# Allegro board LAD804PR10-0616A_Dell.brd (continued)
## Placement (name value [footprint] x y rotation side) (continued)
H7  HOLEA  [H_3P0N]  3 122.3 0 top
H8  HOLEA  [H_3P5-G]  86.9 111.6 0 top
H9  HOLEA  [H_3P5-G]  113.5 134.5 0 top
H10  HOLEA  [H_3P5-G]  136.5 90.5 0 top
H11  HOLEA  [H_3P2]  52.3 133.7 0 top
H12  HOLEA  [H_3P2X2P6]  5 3.6 90 top
H13  HOLEA  [H_6P0]  121.2 136 0 top
HCPU1  HOLEA  [H_3P7X4P3]  101.96 76.01 0 top
HCPU2  HOLEA  [H_3P7]  101.96 31.01 0 top
HCPU3  HOLEA  [H_3P9]  127.36 76.01 0 top
HCPU4  HOLEA  [H_3P7X4P3]  127.36 31.01 90 top
J10  -  [JUMP_43X79]  155.72 18.86 270 bottom
J11  -  [JUMP_43X118]  97.98 98.7 180 bottom
J509  -  [JUMP_43X118]  164.36 5.31 90 bottom
J510  -  [JUMP_43X79]  159.53 5.31 90 bottom
J511  -  [JUMP_43X118]  152.38 25.42 0 bottom
JDIMM1  DEREN_40-42271-26001RHF  [DEREN_40-42271-26001RHF_260P-T]  70.12 87.13 270 bottom
JDIMM2  DEREN_40-42261-26001RHF  [DEREN_40-42261-26001RHF_260P-T]  53.05 87.62 90 bottom
JEDP1  ACES_51540-04001-P01  [ACES_51540-04001-P01_40P]  224.08 50.05 270 bottom
JFAN1  JXT_WB247H-004S10M  [JXT_WB247H-004S10M_4P]  182.74 52.09 47.5 bottom
JH1  ACES_91960-0084N_MX25L3206EM2I  [ACES_91960-0084L_8P-T]  112.17 17.67 270 bottom
JHDD1  ACES_51625-01201-001  [ACES_51625-01201-001_12P]  199.15 17.15 180 bottom
JHDMI1  CONCR_099AKAC19NBLCNF  [CONCR_099AKAC19NBLCNF_19P]  10.45 82.5 90 bottom
JHDT1  SAMTE_ASP-136446-07-B  [SAMTE_ASP-136446-07-B_20P-T]  91.53 70.76 90 top
JHP1  YUQIU_PJ753-F07J1BE-B  [YUQIU_PJ753-F07J1BE-B_7P-T]  11.55 13.52 90 bottom
JIOB1  ACES_51524-0160N-001  [ACES_51524-0160N-001_16P]  185.6 17.6 180 bottom
JKB1  STARC_132C30-100020-A2-R  [STARC_132C30-100020-A2-R_30P]  87.8 9.25 180 bottom
JKBBL1  ACES_51575-00401-001  [ACES_51575-00401-001_4P-T]  116.1 8.72 180 bottom
JLAN1  SANTA_130460-N  [SANTA_130460-N_8P-T]  12.85 113.27 90 bottom
JLED1  ACES_51524-0040N-001  [ACES_51524-0040N-001_4P]  153.7 12.28 180 bottom
JODD1  ACES_50673-0120N-001  [ACES_50673-0120N-001_12P-T]  187.5 47.7 180 bottom
JP2  -  [JUMP_43X39]  114.07 92.78 90 bottom
JP3  2MM  [JUMP_43X39]  28.47 120.72 90 bottom
JP7  -  [JUMP_43X79]  200.47 48.79 180 top
JP12  -  [JUMP_43X39]  36.04 3.32 180 bottom
JP13  -  [JUMP_43X79]  194.84 11.91 90 top
JP14  -  [JUMP_43X39]  37.66 3.32 0 bottom
JPWR1  JXT_FP226H-006S1BM  [JXT_FP226H-006S1BM_6P]  159.15 107.31 90 top
JRTC1  ACES_50271-0020N-001  [ACES_50271-0020N-001_2P]  29.83 5.9 180 bottom
JSPK1  JXT_WB247H-004S10M  [JXT_WB247H-004S10M_4P]  11.8 5.67 180 bottom
JTP1  JXT_FP202DH-008M10M  [JXT_FP202DH-008M10M_8P]  104.9 9.65 180 bottom
JUSB1  ACON_TARA4-9K1311  [ACON_TARA4-9K1311_9P]  14.68 63.2 90 bottom
JUSB2  ACON_TARA4-9K1311  [ACON_TARA4-9K1311_9P]  14.68 41.5 90 bottom
JWLAN1  LCN_DAN05-67406-0100  [LCN_DAN05-67406-0100_67P]  43.05 100.18 0 bottom
L3  MCM1012B900F06BP_4P  [INPAQ_MCM1012B900F06BP_4P]  220.63 34.06 0 bottom
LA1  BLM15BB221SN1D_2P  [MURAT_BLM15BB221SN1D_2P]  29.91 35.07 180 top
LA3  TAI-TECH HCB1005KF-800T20 0402  [R_0402]  35.64 31.26 0 top
LA4  TAI-TECH HCB1005KF-800T20 0402  [R_0402]  35.64 29.99 0 top
LA5  TAI-TECH HCB1005KF-800T20 0402  [R_0402]  35.64 27.45 0 top
LA6  TAI-TECH HCB1005KF-800T20 0402  [R_0402]  35.64 28.72 0 top
LA7  BLM15PX330SN1D_2P  [MURAT_BLM15PX330SN1D_2P]  21.61 14.93 270 bottom
LA8  0_0402_5%  [R_0402]  22.63 13.36 90 top
LA9  0_0402_5%  [R_0402]  22.63 17.66 270 top
LA10  BLM15PX330SN1D_2P  [MURAT_BLM15PX330SN1D_2P]  21.61 17.66 270 bottom
LC22  FBMA-L11-201209-121LMA50T_0805  [KC_FBMA-L11-201209-121LMA50_2P]  86.63 37.09 270 top
LE3  FBMA-L11-160808-800LMT_0603  [KC_FBMA-L11-160808-800LMT_2P]  166.28 35.59 180 top
LE4  FBMA-L11-160808-800LMT_0603  [KC_FBMA-L11-160808-800LMT_2P]  168.54 26.05 180 top
LI1  HCM1012GH900BP_4P  [INPAQ_HCM1012GH900BP_4P]  18.95 85.46 0 top
LI2  HCM1012GH900BP_4P  [INPAQ_HCM1012GH900BP_4P]  17.81 88.09 0 top
LI3  HCM1012GH900BP_4P  [INPAQ_HCM1012GH900BP_4P]  17.87 82.46 0 top
LI4  HCM1012GH900BP_4P  [INPAQ_HCM1012GH900BP_4P]  18.83 79.77 0 top
LU1  HCM1012GD670A05P_4P  [INPAQ_HCM1012GD670A05P_4P]  22.25 58.43 0 top
LU2  HCM1012GD670A05P_4P  [INPAQ_HCM1012GD670A05P_4P]  22.25 60.47 0 top
LU3  MCM1012B900F06BP_4P  [INPAQ_MCM1012B900F06BP_4P]  24.24 55.39 0 top
LU4  HCM1012GD670A05P_4P  [INPAQ_HCM1012GD670A05P_4P]  22.25 39.13 0 top
LU5  HCM1012GD670A05P_4P  [INPAQ_HCM1012GD670A05P_4P]  22.25 41.16 0 top
LU6  MCM1012B900F06BP_4P  [INPAQ_MCM1012B900F06BP_4P]  22.25 35.83 0 top
LU7  MCM1012B900F06BP_4P  [INPAQ_MCM1012B900F06BP_4P]  160.41 15.76 180 bottom
LU8  MCM1012B900F06BP_4P  [INPAQ_MCM1012B900F06BP_4P]  183.09 19.46 90 bottom
LV2  BLM15BD121SN1D_0402  [R_0402]  98.5 111.52 0 top
LV3  BLM15BD121SN1D_0402  [R_0402]  98.11 115.08 0 top
LV4  BLM15BD121SN1D_0402  [R_0402]  95.77 115.84 0 bottom
LV6  BLM15BD221SN1D_2P  [MURAT_BLM15BB221SN1D_2P]  115.84 102.53 90 top
LV7  BLM15BD121SN1D_0402  [R_0402]  120.21 87.9 0 top
LV8  BLM15BD121SN1D_0402  [R_0402]  120.21 86.89 0 top
LX1  HCB2012KF-221T30_2P  [TAI-T_HCB2012KF-221T30_2P]  224.1 42.9 90 top
NOREF  -  []  204.13 19.89 0 top
NOREF#2  -  []  206.6 47.9 0 top
NOREF#3  -  []  -3.98 167.79 0 top
NOREF#4  -  []  3 122.3 0 top
NOREF#5  -  []  141.9 6.3 0 top
NOREF#6  -  []  82.34 54.86 90 top
NOREF#7  -  []  5 3.6 0 top
NOREF#8  -  []  113.5 134.5 0 top
NOREF#9  -  []  166 99.8 0 top
NOREF#10  -  []  127.36 31.01 0 top
NOREF#11  -  []  101.96 76.01 0 top
NOREF#12  -  []  52.3 133.7 0 top
NOREF#13  -  []  136.5 90.5 0 top
NOREF#14  -  []  127.36 76.01 0 top
NOREF#15  -  []  86.9 111.6 0 top
NOREF#16  -  []  18.4 4.3 0 top
NOREF#17  -  []  141.9 61.2 0 top
NOREF#18  -  []  148.04 87.37 0 top
NOREF#19  -  []  68.73 -35.54 0 top
NOREF#20  -  []  101.96 31.01 0 top
NOREF#21  -  []  121.2 136 0 top
NOREF#22  -  []  8.7 122.3 0 top
NOREF#23  -  []  -167.62 44.53 180 bottom
NOREF#24  -  []  81.86 29.99 180 bottom
PBATT1  -  [ACES_50458-01001-P01_10P-T]  225.89 17.6 180 bottom
PC1  1000P_0402_50V7K  [C_0402]  157.51 123.91 180 top
PC2  0.1U_0402_25V7K  [C_0402]  157.51 122.96 180 top
PC3  1000P_0402_50V7K  [C_0402]  156.75 118.77 180 top
PC4  0.1U_0402_25V7K  [C_0402]  156.75 119.66 180 top
PC7  0.01U_0402_25V7K  [C_0402]  206.84 22.47 270 bottom
PC8  1000P_0402_50V7K  [C_0402]  206.82 19.7 90 bottom
PC14  .1U_0402_16V7K  [C_0402]  160.04 97.6 90 top
PC16  .1U_0402_16V7K  [C_0402]  156.16 103.22 0 top
PC100  1000P_0402_50V7K  [C_0402]  176.42 50.49 90 top
PC102  0.1U_0402_10V7K  [C_0402]  172.23 50.89 270 bottom
PC103  2200P_0402_50V7K  [C_0402]  177.44 50.49 90 bottom
PC104  10U_0805_25V6K  [C_0805]  178.43 50.06 0 top
PC105  10U_0805_25V6K  [C_0805]  178.43 50.06 0 bottom
PC106  22U_0805_6.3V6M  [C_0805]  162.33 48.44 90 top
PC107  22U_0805_6.3V6M  [C_0805]  166.05 45.23 0 top
PC108  22U_0805_6.3V6M  [C_0805]  166.05 48.66 0 top
PC109  22U_0805_6.3V6M  [C_0805]  166.05 46.94 0 top
PC110  22U_0805_6.3V6M  [C_0805]  164.1 48.44 90 top
PC111  4.7U_0603_6.3V6M  [C_0603]  173.76 43.83 180 bottom
PC112  680P_0603_50V7K  [C_0603]  170.39 45.93 270 top
PC113  1000P_0402_25V8J  [C_0402]  176.04 43.91 270 bottom
PC114  0.1U_0402_10V7K  [C_0402]  195.09 41.6 270 bottom
PC115  1000P_0402_50V7K  [C_0402]  202.78 37.94 270 bottom
PC116  2200P_0402_50V7K  [C_0402]  201.76 37.94 270 bottom
PC117  10U_0805_25V6K  [C_0805]  200.43 38.21 270 top
PC118  10U_0805_25V6K  [C_0805]  200.43 38.21 270 bottom
PC119  4.7U_0603_6.3V6M  [C_0603]  194.03 34.07 270 bottom
PC120  22U_0805_6.3V6M  [C_0805]  188.07 35.58 180 top
PC121  22U_0805_6.3V6M  [C_0805]  188.07 37.36 180 top
PC122  22U_0805_6.3V6M  [C_0805]  193.17 33.44 0 top
PC123  22U_0805_6.3V6M  [C_0805]  191.19 35.58 0 top
PC124  22U_0805_6.3V6M  [C_0805]  191.19 37.36 0 top
PC125  680P_0603_50V7K  [C_0603]  187.15 39.64 180 top
PC126  4.7U_0603_6.3V6M  [C_0603]  195.27 34.08 270 bottom
PC127  1000P_0402_25V8J  [C_0402]  198.16 33.88 270 bottom
PC128  4.7U_0402_6.3V6M  [C_0402]  193 40.52 90 top
PC130  1000P_0402_50V7K  [C_0402]  176.55 50.49 90 bottom
PC131  1000P_0402_50V7K  [C_0402]  177.31 50.49 90 top
PC132  1000P_0402_50V7K  [C_0402]  201.76 37.94 270 top
PC133  1000P_0402_50V7K  [C_0402]  202.78 37.94 270 top
PC200  0.1U_0402_10V7K  [C_0402]  84.79 106.97 270 bottom
PC201  2200P_0402_50V7K  [C_0402]  81.1 107.33 0 bottom
PC202  0.1U_0402_10V7K  [C_0402]  87.65 99.86 270 bottom
PC203  0.1U_0402_10V7K  [C_0402]  88.54 99.86 270 bottom
PC204  1U_0603_10V6K  [C_0603]  82.38 102.82 0 bottom
PC205  10U_0805_6.3V6K  [C_0805]  92.48 105.15 90 bottom
PC206  10U_0805_25V6K  [C_0805]  80.37 105.86 0 top
PC207  680P_0402_50V7K  [C_0402]  77.88 103.59 180 top
PC208  0.1U_0402_25V6  [C_0402]  81.1 108.35 0 bottom
PC209  1U_0603_10V6K  [C_0603]  83.78 99.08 180 bottom
PC210  0.033U_0402_16V7K  [C_0402]  90.3 102.64 0 bottom
PC211  10U_0805_6.3V6K  [C_0805]  90.7 105.15 90 bottom
PC212  10U_0805_25V6K  [C_0805]  80.7 105.94 0 bottom
PC213  .1U_0402_16V7K  [C_0402]  90.3 101.75 0 bottom
PC214  220P_0402_25V8J  [C_0402]  90.31 99.93 90 bottom
PC215  22U_0603_6.3V6M  [C_0603]  66.82 105.75 90 top
PC216  22U_0603_6.3V6M  [C_0603]  65.55 105.75 90 top
PC217  22U_0603_6.3V6M  [C_0603]  65.55 105.75 90 bottom
PC218  22U_0603_6.3V6M  [C_0603]  64.28 105.75 90 bottom
PC219  22U_0603_6.3V6M  [C_0603]  64.28 105.75 90 top
PC220  22U_0603_6.3V6M  [C_0603]  66.82 105.75 90 bottom
PC230  1000P_0402_50V7K  [C_0402]  80.08 108.27 0 top
PC231  2200P_0402_50V7K  [C_0402]  80.08 107.26 0 top
PC301  0.1U_0402_16V7K  [C_0402]  159.28 30.55 90 bottom
PC302  0.1U_0402_25V6  [C_0402]  155.46 34.08 0 top
PC303  2200P_0402_50V7K  [C_0402]  155.46 34.97 0 top
PC304  10U_0805_25V6K  [C_0805]  153.73 33.07 270 top
PC305  0.1U_0402_10V7K  [C_0402]  159.79 37.05 270 top
PC306  1U_0603_10V6K  [C_0603]  161.06 35.9 90 top
PC307  220U_D2_2VY_R15M  [C_D2]  141.31 33.27 90 bottom
PC308  10U_0805_25V6K  [C_0805]  155.51 33.07 270 top
PC309  680P_0402_50V7K  [C_0402]  152.5 31.39 180 bottom
PC310  220U_D2_2VY_R15M  [C_D2]  140.97 28.66 0 bottom
PC320  1000P_0402_50V7K  [C_0402]  151.4 33.11 270 top
PC321  1000P_0402_50V7K  [C_0402]  152.29 33.11 270 top
PC401  1U_0402_6.3V6K  [C_0402]  97.76 17.29 180 bottom
PC402  10U_0805_10V6K  [C_0805]  95.02 16.17 270 bottom
PC403  0.1U_0402_10V6K  [C_0402]  97.76 15 180 bottom
PC404  0.01U_0402_25V7K  [C_0402]  106.95 16.73 270 bottom
PC405  10U_0805_10V6K  [C_0805]  106.95 17.84 90 bottom
PC601  22U_0603_6.3V6M  [C_0603]  40.34 106.7 270 bottom
PC602  0.1U_0402_10V7K  [C_0402]  35.58 103.6 270 bottom
PC603  22P_0402_50V8J  [C_0402]  35.58 106.24 90 bottom
PC604  680P_0402_50V7K  [C_0402]  40.54 102.26 90 top
PC605  22U_0603_6.3V6M  [C_0603]  36.79 98.82 180 top
PC606  22U_0603_6.3V6M  [C_0603]  36.79 97.55 180 top
PC607  22U_0603_6.3V6M  [C_0603]  41.8 96.86 90 bottom
PC705  2200P_0402_25V7K  [C_0402]  212.99 31.08 0 top
PC708  0.1U_0402_25V6  [C_0402]  214.28 47.26 180 top
PC711  0.01UF_0402_25V7K  [C_0402]  217.27 37.56 90 bottom
PC721  0.22U_0402_16V7K  [C_0402]  207.59 41.04 0 top
PC742  5600P_0402_25V7K  [C_0402]  156.62 108.23 180 bottom
PC744  0.1U_0402_25V6  [C_0402]  158.57 109.24 0 bottom
PC747  0.1U_0402_25V6  [C_0402]  214.45 38.88 0 top
PC748  0.1U_0402_25V7K  [C_0402]  218.97 44.29 90 top
PC749  2200P_0402_25V7K  [C_0402]  218.92 46.56 180 bottom
PC750  0.22U_0603_25V7K  [C_0603]  212.05 37.93 0 top
PC751  560P_0402_50V7K  [C_0402]  217.83 48.1 270 top
PC752  0.015U_0402_25V7K  [C_0402]  217.9 48.34 180 bottom
PC753  10P_0402_50V8J  [C_0402]  216.12 49.04 180 top
PC757  1U_0603_25V6  [C_0603]  213.06 43.58 180 bottom
PC760  10U_0805_25V6K  [C_0805]  212.28 33.48 0 bottom
PC761  10U_0805_25V6K  [C_0805]  217.13 25.4 0 bottom
PC762  10U_0805_25V6K  [C_0805]  212.28 32.47 0 top
PC763  10U_0805_25V6K  [C_0805]  212.28 34.24 0 top
PC764  10U_0805_25V6K  [C_0805]  212.28 35.26 0 bottom
PC765  0.1U_0402_25V7K  [C_0402]  212.16 35.58 0 top
PC766  10U_0805_25V6K  [C_0805]  217.13 23.69 0 bottom
PC767  680P_0603_50V7K  [C_0603]  216.49 32.15 180 bottom
PC768  1U_0402_16V6K  [C_0402]  204.54 42.44 0 top
PC769  1U_0402_16V6K  [C_0402]  204.54 41.42 0 top
PC775  10U_0805_25V6K  [C_0805]  216.52 21.83 270 bottom
PC776  10U_0805_25V6K  [C_0805]  214.82 21.83 270 bottom
PC777  0.1U_0402_25V7K  [C_0402]  217.88 22.1 270 bottom
PC778  10U_0805_25V6K  [C_0805]  213 21.89 270 bottom
PC779  0.1U_0402_25V7K  [C_0402]  205.77 28.61 0 top
PC780  1000P_0402_50V7K  [C_0402]  212.16 37.61 0 bottom
PC781  1000P_0402_50V7K  [C_0402]  213.11 32.02 0 bottom
PC790  0.01U_0402_16V7K  [C_0402]  217.02 50.54 270 top
PC801  4.7U_0805_6.3V6K  [C_0805]  129.22 17.54 0 bottom
PC802  1U_0603_10V6K  [C_0603]  126.58 17.29 0 bottom
PC803  .1U_0402_16V7K  [C_0402]  133.88 13.43 270 bottom
PC804  10U_0603_6.3V6M  [C_0603]  133.88 11.38 270 bottom
PC805  0.1U_0402_10V7K  [C_0402]  138.45 12.51 90 bottom
PC836  330U_2V_M  [C_5X4P5]  94.33 128.12 270 bottom
PC837  330U_2V_M  [C_5X4P5]  87.97 127.99 270 bottom
PC838  330U_2V_M  [C_5X4P5]  86.97 121.43 180 bottom
PC839  330U_2V_M  [C_5X4P5]  81.47 122.19 0 bottom
PC901  1U_0402_6.3V6K  [C_0402]  21.22 102.82 0 bottom
PC902  10U_0805_10V6K  [C_0805]  17.99 99.74 90 bottom
PC903  0.01U_0402_25V7K  [C_0402]  27.07 98.9 270 bottom
PC904  10U_0805_10V6K  [C_0805]  27.45 100.39 90 bottom
PC905  0.1U_0402_10V6K  [C_0402]  18.48 97.8 180 bottom
PC911  22U_0603_6.3V6M  [C_0603]  135.2 82.45 90 bottom
PC912  22U_0603_6.3V6M  [C_0603]  133.89 82.45 90 bottom
PC913  22U_0603_6.3V6M  [C_0603]  132.7 82.47 90 bottom
PC914  22U_0603_6.3V6M  [C_0603]  115.35 54.42 90 top
PC915  22U_0603_6.3V6M  [C_0603]  110.01 53.61 270 top
PC916  22U_0603_6.3V6M  [C_0603]  111.25 53.61 270 top
PC917  22U_0603_6.3V6M  [C_0603]  112.47 53.61 270 top
PC931  22U_0603_6.3V6M  [C_0603]  118.37 59.09 270 top
PC932  22U_0603_6.3V6M  [C_0603]  119.77 63.04 270 top
PC954  470U_X_2VY_R9M  [C_D2]  136.42 74.08 270 bottom
PC955  470U_X_2VY_R9M  [C_D2]  143.02 77.08 90 bottom
PC956  470U_X_2VY_R9M  [C_D2]  138.2 78.35 90 bottom
PC959  470U_X_2VY_R9M  [C_D2]  144.27 47.26 0 bottom
PC960  470U_X_2VY_R9M  [C_D2]  139.68 47.94 90 bottom
PC1000  33U_25V_M  [C_25CL33LD]  158.52 75.3 90 bottom
PC1001  33U_25V_M  [C_25CL33LD]  151.4 75.3 90 bottom
PC1002  10U_0805_25V6K  [C_0805]  158.35 58.95 180 top
PC1003  10U_0805_25V6K  [C_0805]  162.05 52.53 270 bottom
PC1004  330P_0402_50V7K  [C_0402]  170.15 52.34 180 top
PC1006  390P_0402_50V7K  [C_0402]  167.15 53.41 90 top
PC1007  1000P_0402_50V7K  [C_0402]  170.2 55.59 270 top
PC1008  220P_0402_50V8J  [C_0402]  167.1 55.39 180 top
PC1009  0.22U_0402_16V7K  [C_0402]  165.12 54.68 90 top
PC1010  330P_0402_50V7K  [C_0402]  171.99 55.52 180 top
PC1011  0.022U_0402_25V7K  [C_0402]  171.34 56.55 270 bottom
PC1012  0.1U_0603_16V7K  [C_0603]  169.31 56.76 270 bottom
PC1013  680P_0603_50V7K  [C_0603]  152.17 47.33 270 top
PC1014  0.1U_0603_50V7K  [C_0603]  169.18 54.25 0 bottom
PC1015  220P_0402_50V7K  [C_0402]  167.32 55.44 90 bottom
PC1018  1000P_0402_50V7K  [C_0402]  168.73 58.18 0 bottom
PC1037  330P_0402_50V7K  [C_0402]  163.55 68.34 180 top
PC1038  0.22U_0402_16V7K  [C_0402]  160.8 63.47 270 top
PC1039  10U_0805_25V6K  [C_0805]  158.35 64.53 180 top
PC1053  0.1U_0603_16V7K  [C_0603]  170.96 66.76 270 top
PC1054  680P_0603_50V7K  [C_0603]  148.1 64.72 270 top
PC1055  1U_0603_10V6K  [C_0603]  161.75 57.42 180 top
PC1056  2200P_0402_50V7K  [C_0402]  157.45 63.01 180 bottom
PC1057  390P_0402_50V7K  [C_0402]  163.6 66.26 270 top
PC1058  0.01U_0402_50V7K  [C_0402]  163.6 70.43 90 top
PC1059  330P_0402_50V7K  [C_0402]  167.66 65.35 90 top
PC1060  1000P_0402_50V7K  [C_0402]  166.59 66.31 180 top
PC1061  820P_0402_50V7K  [C_0402]  168.68 66.26 270 top
PC1062  1000P_0402_50V7K  [C_0402]  168.73 62.25 0 bottom
PC1063  1U_0603_10V6K  [C_0603]  160.55 59.9 270 top
PC1064  0.1U_0402_25V6K  [C_0402]  169.64 60.22 180 bottom
PC1065  0.1U_0603_50V7K  [C_0603]  169.37 69.61 180 top
PC1066  0.022U_0402_25V7K  [C_0402]  170.4 68.34 180 top
PC1067  10U_0805_25V6K  [C_0805]  158.35 66.57 180 top
PC1068  150P_0402_50V8J  [C_0402]  164.61 66.26 270 top
PC1069  0.1U_0402_25V6K  [C_0402]  157.45 66.06 180 bottom
PC1070  10U_0805_25V6K  [C_0805]  158.35 62.76 180 top
PC1071  2200P_0402_50V7K  [C_0402]  159.8 52.1 270 bottom
PC1072  1000P_0402_50V7K  [C_0402]  160.69 52.1 270 bottom
PC1073  1000P_0402_50V7K  [C_0402]  157.45 61.99 180 bottom
PC1074  1000P_0402_50V7K  [C_0402]  157.45 58.95 180 bottom
PC1075  2200P_0402_50V7K  [C_0402]  157.45 65.04 180 bottom
PC1076  0.1U_0402_25V6K  [C_0402]  157.45 64.03 180 bottom
PC1101  0.1U_0402_25V6K  [C_0402]  49.12 124.93 180 top
PC1103  10U_0805_25V6K  [C_0805]  64.57 127.11 270 bottom
PC1104  10U_0805_25V6K  [C_0805]  64.09 113.28 90 top
PC1105  10U_0805_25V6K  [C_0805]  64.56 113.28 90 bottom
PC1106  2200P_0402_50V7K  [C_0402]  65.87 127.23 270 bottom
PC1107  0.1U_0402_25V6K  [C_0402]  65.88 113.61 90 bottom
PC1108  0.22U_0402_16V7K  [C_0402]  59.72 124.48 180 top
PC1109  680P_0603_50V7K  [C_0603]  69.3 128.03 180 top
PC1110  1U_0603_10V6K  [C_0603]  58.44 128.93 270 top
PC1111  1U_0603_10V6K  [C_0603]  56.03 127.53 90 top
PC1112  10U_0805_25V6K  [C_0805]  64.47 127.11 270 top
PC1113  10U_0805_25V6K  [C_0805]  62.69 127.11 270 top
PC1114  10U_0805_25V6K  [C_0805]  62.31 113.28 90 top
PC1115  2200P_0402_50V7K  [C_0402]  66.78 113.59 90 bottom
PC1116  0.1U_0402_25V6  [C_0402]  66.74 127.23 270 bottom
PC1117  1000P_0402_50V7K  [C_0402]  48.2 120.48 0 top
PC1118  0.22U_0402_16V7K  [C_0402]  59.41 121.68 180 top
PC1119  0.22U_0402_10V6K  [C_0402]  50.18 117.8 90 top
PC1120  0.22U_0402_10V6K  [C_0402]  51.07 117.8 90 top
PC1121  680P_0603_50V7K  [C_0603]  69.04 114.06 180 top
PC1122  1000P_0402_50V7K  [C_0402]  53.92 116.35 0 top
PC1123  180P_0402_50V8J  [C_0402]  57.6 118.71 0 top
PC1124  330P_0402_50V7K  [C_0402]  53.92 118.71 0 top
PC1125  0.033U_0402_16V7K  [C_0402]  50.11 115.66 0 top
PC1126  0.15U_0603_16V7K  [C_0603]  50.25 116.74 0 top
PC1127  390P_0402_50V7K  [C_0402]  58.5 116.91 90 top
PC1128  330P_0402_50V  [C_0402]  57.5 115.02 180 top
PC1129  0.1U_0603_50V7K  [C_0603]  53.99 114.2 0 top
PC1130  820P_0402_50V7K  [C_0402]  53.04 117.8 90 top
PC1131  0.01U_0402_50V7K  [C_0402]  56.61 118.71 180 top
PC1140  2200P_0402_50V7K  [C_0402]  65.8 127.23 270 top
PC1141  0.1U_0402_25V6K  [C_0402]  65.55 113.61 90 top
PC1142  2200P_0402_50V7K  [C_0402]  66.69 127.23 270 top
PC1143  0.1U_0402_25V6  [C_0402]  66.57 113.61 90 top
PC1401  2200P_0402_50V7K  [C_0402]  158.31 94.44 0 bottom
PC1402  0.1U_0402_25V6  [C_0402]  158.31 95.33 0 bottom
PC1403  10U_0805_25V6K  [C_0805]  157.41 91.27 0 bottom
PC1404  0.1U_0402_25V6  [C_0402]  159.44 85.51 90 bottom
PC1405  1U_0402_6.3V6K  [C_0402]  152.52 84.64 270 bottom
PC1406  2.2U_0402_6.3V6M  [C_0402]  151.63 84.64 270 bottom
PC1407  0.1U_0402_10V7K  [C_0402]  153.69 92.42 270 bottom
PC1408  680P_0603_50V7K  [C_0603]  148.01 91.74 180 bottom
PC1409  330P_0402_50V7K  [C_0402]  155.17 83.74 0 bottom
PC1411  22U_0603_6.3V6M  [C_0603]  142.74 86.03 180 bottom
PC1412  22U_0603_6.3V6M  [C_0603]  142.74 87.23 180 bottom
PC1413  22U_0603_6.3V6M  [C_0603]  142.74 88.44 180 bottom
PC1414  22U_0603_6.3V6M  [C_0603]  142.74 89.65 180 bottom
PC1420  2200P_0402_50V7K  [C_0402]  158.28 92.63 0 bottom
PC1421  0.1U_0402_25V6  [C_0402]  158.28 93.52 0 bottom
PD2  -  [TVNST52302AB0_SOT523-3]  214.65 12.02 180 top
PD3  -  [TVNST52302AB0_SOT523-3]  217.95 12.02 180 top
PD4  -  [TVNST52302AB0_SOT523-3]  157.66 121.75 270 bottom
PD5  -  [BAV99W_SC70-3]  165.88 128.84 180 bottom
PD6  -  [BAV99W_SC70-3]  162.23 126.52 270 bottom
PD102  -  [SDMK0340L-7-F_SOD323-2]  191.65 42.13 270 top
PD704  -  [LRB715FT1G_SOT323-3]  199.6 44.21 90 top
PH1  100K_0402_1%_TSM0B104F4251RZ  [R_0402]  120.68 41.36 180 top
PH1000  10K_0402_5%_ERTJ0ER103J  [R_0402]  147.4 57.54 90 bottom
PH1001  470K_0402_5%_TSM0B474J4702RE  [R_0402]  161.79 54.65 270 bottom
PH1002  470K_0402_5%_TSM0B474J4702RE  [R_0402]  162.25 72.15 0 bottom
PH1003  10K_0402_5%_ERTJ0ER103J  [R_0402]  142.06 74.44 0 bottom
PH1101  470K_0402_5%_TSM0B474J4702RE  [R_0402]  69.76 108.73 180 bottom
PH1102  10K_0402_5%_ERTJ0ER103J  [R_0402]  74.33 108.73 180 bottom
PJP1  JUMP_43X79  [JUMP_43X79-NPM]  159.2 119.84 90 top
PJP2  JUMP_43X79  [JUMP_43X79-NPM]  165.73 120.9 0 top
PJP3  JUMP_43X79  [JUMP_43X79-NPM]  209.49 20.51 90 bottom
PJP102  -  [JUMP_43X118]  162.83 45.02 270 top
PJP103  -  [JUMP_43X118]  189.5 33.33 270 top
PJP105  JUMP_43X79  [JUMP_43X79-NPM]  174.33 54.16 270 bottom
PJP106  JUMP_43X79  [JUMP_43X79-NPM]  198.86 42.58 270 bottom
PJP200  -  [JUMP_43X118]  65.11 101.79 270 top
PJP201  -  [JUMP_43X118]  70.38 101.81 270 top
PJP203  -  [JUMP_43X79]  93.56 102.34 90 bottom
PJP206  JUMP_43X79  [JUMP_43X79-NPM]  78.77 111.53 90 top
PJP301  -  [JUMP_43X118]  145.94 25.02 270 bottom
PJP302  -  [JUMP_43X118]  140.67 25.02 270 bottom
PJP303  JUMP_43X79  [JUMP_43X79-NPM]  156.84 39.26 180 bottom
PJP401  -  [JUMP_43X79]  91.93 15.77 0 bottom
PJP402  -  [JUMP_43X79]  109.3 14.22 270 bottom
PJP601  -  [JUMP_43X79]  39.2 109.53 270 bottom
PJP602  -  [JUMP_43X79]  38.33 95.8 270 top
PJP701  JUMP_43X118  [JUMP_43X118-NPM]  206.94 37.01 0 bottom
PJP801  -  [JUMP_43X79]  130.83 20.63 270 bottom
PJP802  -  [JUMP_43X79]  131.08 8.61 90 bottom
PJP803  -  [JUMP_43X79]  126.72 20.34 0 bottom
PJP901  -  [JUMP_43X79]  14.71 98.7 0 bottom
PJP902  -  [JUMP_43X79]  29.7 98.95 0 bottom
PJP1001  JUMP_43X79  [JUMP_43X79-NPM]  164.65 75.46 180 bottom
PJP1101  JUMP_43X79  [JUMP_43X79-NPM]  65.67 131.57 270 bottom
PJP1401  JUMP_43X79  [JUMP_43X79-NPM]  157.92 100.35 270 bottom
PJP1402  -  [JUMP_43X118]  143.5 91.64 90 bottom
PJPDC1  ACES_50458-00601-001  [ACES_50458-00601-001_6P-T]  169.1 124.25 180 top
PL1  HCB3225KF-151T50_2P  [5A_Z150_1210_2P]  159.19 121.71 270 top
PL2  BLM15AG102SN1D_2P  [MURAT_BLM15AG102SN1D_2P]  162.24 122.38 0 top
PL3  HCB3225KF-151T50_2P  [5A_Z150_1210_2P]  209.46 22.44 270 bottom
PL4  HCB3225KF-151T50_2P  [5A_Z150_1210_2P]  167.61 120.93 180 top
PL100  1.5UH_9A_20%_7X7X3_M  [L_7X7X3_M_2P]  171.07 46.94 180 bottom
PL101  2.2UH_7.8A_20%_7X7X3_M  [L_7X7X3_M_2P]  189.76 41.4 270 bottom
PL102  HCB3225KF-151T50_2P  [5A_Z150_1210_2P]  174.33 54.96 270 bottom
PL103  HCB3225KF-151T50_2P  [5A_Z150_1210_2P]  198.93 43.35 270 bottom
PL200  1UH_11A_20%_7X7X3_M  [L_7X7X3_M_2P]  69.64 104.16 0 bottom
PL201  HCB3225KF-151T50_2P  [5A_Z150_1210_2P]  78.79 113.38 270 top
PL301  HCB3225KF-151T50_2P  [5A_Z150_1210_2P]  154.89 39.27 0 bottom
PL302  1UH_11A_20%_7X7X3_M  [L_7X7X3_M_2P]  147.59 39.24 270 bottom
PL601  1UH_6.6A_20%_5X5X3_M  [L_5X5X3_M_2P]  38.18 101.06 270 bottom
PL700  4.7UH_5.5A_20%_7X7X3_M  [L_7X7X3_M_2P]  208.94 31.68 270 bottom
PL704  1UH_PCMB053T-1R0MS_7A_20%  [L_5X5X3_M_2P]  205.32 36.98 0 bottom
PL1001  HCB3225KF-151T50_2P  [5A_Z150_1210_2P]  162.75 75.46 0 bottom
PL1002  0.15UH_29A_20%_7X7X4_MOLDING  [L_7X7X4_M]  151.64 53.36 180 bottom
PL1004  0.15UH_29A_20%_7X7X4_MOLDING  [L_7X7X4_M]  147.06 70.12 180 bottom
PL1101  HCB3225KF-151T50_2P  [5A_Z150_1210_2P]  65.6 129.69 90 bottom
PL1102  0.22UH_24A_20%_7X7X4_MOLDING  [L_7X7X4_M]  76.8 129.81 0 bottom
PL1103  0.22UH_24A_20%_7X7X4_MOLDING  [L_7X7X4_M]  78.51 110.78 90 bottom
PL1401  1UH_6.6A_20%_5X5X3_M  [L_5X5X3_M_2P]  151.75 88.17 180 bottom
PL1402  HCB3225KF-151T50_2P  [5A_Z150_1210_2P]  157.94 101.17 270 bottom
PQ1  L2N7002DW1T1G_SC88-6  [2N7002DW-T-R7_SOT363-6]  162.95 90.85 0 top
PQ2  L2N7002DW1T1G_SC88-6  [2N7002DW-T-R7_SOT363-6]  157.52 101.72 180 top
PQ3  -  [L2N7002WT1G_SC70-3]  159.53 99.65 0 top
PQ5  MMST3904-7-F_SOT323  [RHU002N06_SOT323-3]  160.99 127.11 180 bottom
PQ6  FDV301N_G 1N SOT23-3  [FDV301N_NL_SOT23-3]  162.58 121.79 180 bottom
PQ201  -  [AON7934_DFN3X3A8-10]  78.8 104.27 0 bottom
PQ301  AON6552_DFN5X6-8-5  [SIR472DP-T1-GE3_POWERPAK8-5]  150.64 40.35 270 top
PQ302  AON6554_DFN5X6-8-5  [SIR472DP-T1-GE3_POWERPAK8-5]  150.14 30.82 90 top
PQ704  AON7408L_DFN8-5  [SIS412DN-T1-GE3_POWERPAK8-5]  208.77 31.48 0 top
PQ708  AON7506_DFN33-8-5  [SIS412DN-T1-GE3_POWERPAK8-5]  212.85 27.67 90 top
PQ709  -  [L2N7002WT1G_SC70-3]  158 106.62 90 bottom
PQ710  -  [LMUN5113T1G_SOT323-3]  221.1 20.13 0 top
PQ711  -  [LTC015EUBFS8TL_UMT3F]  220.96 24.02 270 top
PQ712  -  [L2N7002WT1G_SC70-3]  216.76 32.48 0 top
PQ717  -  [MDU1512RH_POWERDFN56-8-5]  202.9 30.18 0 top
PQ718  -  [MDU1512RH_POWERDFN56-8-5]  162.14 118.72 0 bottom
PQ720  -  [RUM002N02GT2L_VMT3]  215.67 51.14 0 top
PQ721  -  [RUM002N02GT2L_VMT3]  219.12 50.11 270 top
PQ740  -  [MDU1512RH_POWERDFN56-8-5]  160.16 117 270 bottom
PQ801  L2N7002WT1G_SC70-3  [SSM3K7002FU_SC70-3]  136.67 13.41 0 bottom
PQ1001  AON6552_DFN5X6-8-5  [SIR472DP-T1-GE3_POWERPAK8-5]  154.58 53.49 90 bottom
PQ1002  AON6554_DFN5X6-8-5  [SIR472DP-T1-GE3_POWERPAK8-5]  154.58 46.12 0 top
PQ1003  AON6554_DFN5X6-8-5  [SIR472DP-T1-GE3_POWERPAK8-5]  158.39 46.12 180 bottom
PQ1007  AON6552_DFN5X6-8-5  [SIR472DP-T1-GE3_POWERPAK8-5]  155.59 68.47 90 bottom
PQ1008  AON6554_DFN5X6-8-5  [SIR472DP-T1-GE3_POWERPAK8-5]  150.01 63.64 0 top
PQ1009  AON6554_DFN5X6-8-5  [SIR472DP-T1-GE3_POWERPAK8-5]  153.82 63.64 180 bottom
PQ1101  AON6552_DFN5X6-8-5  [SIR472DP-T1-GE3_POWERPAK8-5]  73.86 131.59 270 bottom
PQ1102  AON6554_DFN5X6-8-5  [SIR472DP-T1-GE3_POWERPAK8-5]  68.01 122.07 90 bottom
PQ1103  AON6554_DFN5X6-8-5  [SIR472DP-T1-GE3_POWERPAK8-5]  67.96 125.88 270 top
PQ1104  AON6552_DFN5X6-8-5  [SIR472DP-T1-GE3_POWERPAK8-5]  73.43 113.94 270 bottom
PQ1105  AON6554_DFN5X6-8-5  [SIR472DP-T1-GE3_POWERPAK8-5]  67.96 120.03 270 top
PQ1106  AON6554_DFN5X6-8-5  [SIR472DP-T1-GE3_POWERPAK8-5]  67.96 116.22 90 bottom
PR2  1M_0402_1%  [R_0402]  164.18 89.33 180 top
PR3  2.2K_0402_5%  [R_0402]  165.99 125.12 0 bottom
PR4  33_0402_5%  [R_0402]  165.04 124.17 0 bottom
PR5  3.3K_1206_5%  [R_1206]  166.49 93.36 270 top
PR6  100K_0402_1%  [R_0402]  160.13 122.81 270 bottom
PR7  1M_0402_1%  [R_0402]  163.39 94 0 top
PR8  10K_0402_1%  [R_0402]  165.06 126.02 270 bottom
PR9  15K_0402_1%  [R_0402]  161.26 130.32 180 bottom
PR10  1M_0402_1%  [R_0402]  161.82 89.98 90 top
PR11  100K_0402_1%  [R_0402]  160.98 125.63 0 bottom
PR12  0_0402_5%  [R_0402]  166.91 88.41 90 top
PR13  0_0402_5%  [R_0402]  165.99 88.43 90 top
PR14  0_0402_5%  [R_0402]  165.1 88.43 90 top
PR15  200_0402_5%  [R_0402]  218.46 15.46 270 top
PR16  10K_0402_1%  [R_0402]  219.48 14.55 90 top
PR18  100_0402_5%  [R_0402]  214.14 15.46 270 top
PR20  100_0402_5%  [R_0402]  215.16 15.46 270 top
PR24  15K_0402_1%  [R_0402]  170.97 36.15 180 top
PR28  10K_0402_1%  [R_0402]  157.08 104.16 180 top
PR29  100K_0402_1%  [R_0402]  157.94 103.22 0 top
PR31  1M_0402_1%  [R_0402]  158.01 98.52 270 top
PR32  100K_0402_1%  [R_0402]  159.02 98.52 270 top
PR33  1M_0402_1%  [R_0402]  156.99 97.6 90 top
PR100  2.2_0603_5%  [R_0603]  174.58 50.37 180 bottom
PR102  499K_0402_1%  [R_0402]  176.42 45.15 90 top
PR103  499K_0402_1%  [R_0402]  178.57 45.29 0 top
PR106  4.7_1206_5%  [R_1206]  170.71 49.74 270 top
PR107  10K_0402_1%  [R_0402]  179.48 46.25 180 bottom
PR108  1K_0402_5%  [R_0402]  175.03 42.99 90 bottom
PR109  150K_0402_1%  [R_0402]  177.06 43.91 270 bottom
PR110  150K_0402_1%  [R_0402]  178.07 43.91 270 bottom
PR111  2.2_0603_5%  [R_0603]  196.21 40.24 90 bottom
PR112  4.7_1206_5%  [R_1206]  188.74 42.25 270 top
PR113  10K_0402_1%  [R_0402]  198.65 36.14 90 top
PR114  2.2K_0402_5%  [R_0402]  194.08 42.89 270 top
PR115  150K_0402_1%  [R_0402]  196.35 34.18 0 bottom
PR116  0_0402_5%  [R0402_0OHM]  190.27 42.89 270 top
PR117  1K_0402_5%  [R_0402]  197.26 32.66 180 bottom
PR118  150K_0402_1%  [R_0402]  199.05 33.88 270 bottom
PR120  0_0402_5%  [R0402_0OHM]  194.08 39.69 90 top
PR121  0_0402_5%  [R0402_0OHM]  178.83 45.17 315 bottom
PR122  1M_0402_5%  [R_0402]  193 39.59 270 top
PR200  0_0603_5%  [R0603_0OHM]  85.74 106.77 0 bottom
PR201  0_0402_5%  [R0402_0OHM]  86.76 98.94 90 bottom
PR202  0_0402_5%  [R0402_0OHM]  89.43 98.94 90 bottom
PR203  4.7_1206_5%  [R_1206]  76.35 102.13 0 top
PR204  100K_0402_1%  [R_0402]  90.32 99.1 270 bottom
PR205  11K_0402_1%  [R_0402]  82.37 103.9 0 bottom
PR206  5.1_0603_5%  [R_0603]  82.38 100.35 0 bottom
PR207  60.4K_0402_1%  [R_0402]  91.19 99.94 90 bottom
PR208  453K_0402_1%  [R_0402]  85.87 98.94 90 bottom
PR209  10K_0402_1%  [R_0402]  84.98 98.94 90 bottom
PR210  2.2_0603_5%  [R_0603]  83.78 101.55 180 bottom
PR211  10_0402_1%  [R_0402]  85.82 100.86 180 top
PR212  0_0402_5%  [R0402_0OHM]  85.82 99.97 180 top
PR301  0_0402_5%  [R0402_0OHM]  157.44 28.01 90 top
PR302  100K_0402_5%  [R_0402]  156.55 28.01 90 top
PR303  0_0603_5%  [R0603_0OHM]  158.52 35.9 90 top
PR304  42.2K_0402_1%  [R_0402]  157.75 31.46 270 bottom
PR305  4.7_1206_5%  [R_1206]  152.48 35.26 270 bottom
PR306  470K_0402_1%  [R_0402]  161.06 30.55 90 bottom
PR307  3.48K_0402_1%  [R_0402]  159.41 28.92 270 top
PR308  10K_0402_1%  [R_0402]  158.52 28.73 270 top
PR309  10_0402_1%  [R_0402]  161.51 28.97 180 top
PR310  0_0402_5%  [R_0402]  160.6 27.96 0 top
PR311  0_0402_5%  [R_0402]  159.52 26.69 0 top
PR401  8.87K_0402_1%  [R_0402]  107.97 16.73 270 bottom
PR402  10K_0402_1%  [R_0402]  106.95 14.89 270 bottom
PR403  0_0402_5%  [R_0402]  96.84 13.99 0 bottom
PR601  0_0402_5%  [R0402_0OHM]  33.55 102.68 90 bottom
PR602  1M_0402_5%  [R_0402]  34.56 102.68 90 bottom
PR603  10_0402_5%  [R_0402]  34.61 105.17 0 bottom
PR604  20K_0402_1%  [R_0402]  34.56 107.16 270 bottom
PR605  10K_0402_1%  [R_0402]  33.55 107.16 270 bottom
PR606  4.7_1206_5%  [R_1206]  37.04 100.75 0 top
PR703  0.01_1206_1%  [R_1206_4P]  161.5 110.83 0 bottom
PR727  0_0402_5%  [R_0402]  216.3 44.93 270 bottom
PR729  392K_0402_1%  [R_0402]  218.18 37.56 90 bottom
PR731  158K_0402_1%  [R_0402]  217.11 39.9 0 top
PR732  53.6K_0402_1%  [R_0402]  217.13 38.7 270 top
PR737  3M_0402_5%  [R_0402]  160.42 109.26 270 bottom
PR738  1M_0402_1%  [R_0402]  161.08 107.42 270 bottom
PR740  2_0402_5%  [R_0402]  214.4 36.9 90 top
PR741  100K_0402_1%  [R_0402]  218.02 40.78 180 top
PR742  2_0402_5%  [R_0402]  213.38 48.2 90 top
PR743  10_1206_5%  [R_1206]  202.84 41.99 180 top
PR745  100_0402_1%  [R_0402]  211.17 38.05 180 top
PR749  200K_0402_1%  [R_0402]  214.32 47.2 0 bottom
PR750  200K_0402_1%  [R_0402]  214.32 46.31 0 bottom
PR751  75K_0402_1%  [R_0402]  212.49 48.1 270 top
PR752  66.5K_0402_1%  [R_0402]  213.3 44.91 0 bottom
PR753  182K_0402_1%  [R_0402]  215.41 44.01 90 bottom
PR754  100_0402_1%  [R_0402]  216.94 48.1 270 top
PR755  102K_0402_1%  [R_0402]  216.05 48.1 270 top
PR756  10K_0402_1%  [R_0402]  215.21 49.04 0 bottom
PR757  100K_0402_1%  [R_0402]  211.6 48.1 270 top
PR760  4.7_0402_5%  [R_0402]  206.52 42.39 270 top
PR761  0_0603_5%  [R0603_0OHM]  209.81 41.12 270 top
PR762  4.02K_0402_1%  [R_0402]  160.37 121 270 bottom
PR763  4.02K_0402_1%  [R_0402]  161.37 109.26 270 bottom
PR764  10K_0402_1%  [R_0402]  215.16 48.1 270 top
PR765  0.01_1206_1%  [R_1206_4P]  214.72 28.56 270 bottom
PR766  4.7_1206_5%  [R_1206]  213.57 30.18 0 bottom
PR769  0_0402_5%  [R0402_0OHM]  218.02 41.67 180 top
PR770  0_0402_5%  [R0402_0OHM]  218.02 42.56 180 top
PR771  2.2_0603_5%  [R_0603]  208.74 39.9 180 top
PR772  0_0402_5%  [R0402_0OHM]  215.41 36.9 90 top
PR773  0_0603_5%  [R0603_0OHM]  206.78 26.24 90 top
PR774  1K_0402_1%  [R_0402]  218.02 44.34 180 top
PR775  0_0402_5%  [R0402_0OHM]  218.02 45.23 180 top
PR776  0_0402_5%  [R0402_0OHM]  214.27 48.2 90 top
PR777  0_0402_5%  [R_0402]  218.02 43.45 180 top
PR778  0_0402_5%  [R0402_0OHM]  159.48 110.2 180 bottom
PR779  0_0402_5%  [R0402_0OHM]  212.44 49.04 180 top
PR780  0_0603_5%  [R_0603]  219.29 20.8 90 top
PR781  10K_0402_5%  [R_0402]  214.26 48.09 90 bottom
PR790  160K_0402_1%  [R_0402]  217.11 51.45 0 top
PR791  10K_0402_5%  [R_0402]  217.11 52.34 0 top
PR801  0_0402_5%  [R0402_0OHM]  139.47 13.43 270 bottom
PR802  1.33K_0402_1%  [R_0402]  133.88 15.21 270 bottom
PR803  1K_0402_1%  [R_0402]  134.89 13.43 270 bottom
PR901  21.5K_0402_1%  [R_0402]  28.09 98.9 270 bottom
PR902  10K_0402_1%  [R_0402]  28.04 96.92 180 bottom
PR903  0_0402_5%  [R0402_0OHM]  17.57 98.72 0 bottom
PR1000  2K_0402_1%  [R_0402]  169.18 53.41 90 top
PR1002  10_0402_5%  [R_0402]  134.84 67.46 180 top
PR1003  1.78K_0402_1%  [R_0402]  171.17 53.61 180 top
PR1004  137K_0402_1%  [R_0402]  168.17 54.32 270 top
PR1005  34K_0402_1%  [R_0402]  166.14 54.32 270 top
PR1006  0_0402_5%  [R0402_0OHM]  172.18 54.63 180 top
PR1007  301_0402_1%  [R_0402]  168.88 55.39 180 top
PR1008  2.2_0603_5%  [R_0603]  163.98 56.41 270 top
PR1009  2.61K_0402_1%  [R_0402]  149.07 57.17 180 top
PR1010  4.7_1206_5%  [R_1206]  152.17 51.14 270 top
PR1011  11K_0402_1%  [R_0402]  149.07 58.18 180 top
PR1012  3.65K_0603_1%  [R_0603]  150.64 57.74 180 bottom
PR1013  243_0402_1%  [R_0402]  168.24 55.44 90 bottom
PR1014  1_0402_1%  [R_0402]  148.29 58.45 270 bottom
PR1015  100_0402_1%  [R_0402]  168.24 54.54 180 bottom
PR1016  13.3K_0402_1%  [R_0402]  171.42 57.68 180 top
PR1018  133K_0402_1%  [R_0402]  168.73 59.2 0 bottom
PR1021  100K_0402_1%  [R_0402]  172.18 59.71 180 top
PR1023  0_0402_5%  [R0402_0OHM]  172.18 60.72 180 top
PR1026  1_0603_5%  [R_0603]  161.82 59.9 270 top
PR1028  0_0402_5%  [R_0402]  172.12 59.71 180 bottom
PR1047  2.15K_0402_1%  [R_0402]  166.59 65.3 180 top
PR1051  10_0402_5%  [R_0402]  133.93 68.41 0 top
PR1065  2K_0402_1%  [R_0402]  164.61 67.38 90 top
PR1066  294_0402_1%  [R_0402]  169.69 66.26 270 top
PR1067  10_0402_5%  [R_0402]  164.61 70.43 90 top
PR1068  1_0402_1%  [R_0402]  143.83 74.44 0 bottom
PR1069  0_0402_5%  [R0402_0OHM]  163.65 69.36 0 top
PR1070  100K_0402_5%  [R_0402]  161.31 66.26 270 top
PR1071  11K_0402_1%  [R_0402]  145 76.22 180 top
PR1072  100_0402_1%  [R_0402]  169.39 67.33 180 top
PR1073  301_0402_1%  [R_0402]  165.63 67.38 90 top
PR1074  4.7_1206_5%  [R_1206]  148.1 68.66 270 top
PR1075  0_0402_5%  [R0402_0OHM]  166.64 67.38 90 top
PR1076  133K_0402_1%  [R_0402]  168.73 61.23 0 bottom
PR1077  137K_0402_1%  [R_0402]  163.55 67.33 180 top
PR1078  210K_0402_1%  [R_0402]  162.58 65.35 90 top
PR1079  2.61K_0402_1%  [R_0402]  145 77.17 180 top
PR1080  13.3K_0402_1%  [R_0402]  171.22 63.72 270 top
PR1081  10K_0402_1%  [R_0402]  167.66 66.26 270 bottom
PR1082  2.2_0603_5%  [R_0603]  162.07 62.57 90 top
PR1084  3.65K_0603_1%  [R_0603]  146.13 75.77 270 bottom
PR1085  0_0402_5%  [R0402_0OHM]  172.18 61.74 180 top
PR1086  150K_0402_1%  [R_0402]  171.42 56.66 180 top
PR1087  150K_0402_1%  [R_0402]  172.23 62.81 90 top
PR1101  100K_0402_1%  [R_0402]  50.22 128.46 270 top
PR1103  0_0603_5%  [R0603_0OHM]  58.25 125.56 0 top
PR1104  10K_0402_1%  [R_0402]  49.12 117.82 180 top
PR1105  10K_0402_1%  [R_0402]  54.06 128.43 270 top
PR1106  10K_0402_1%  [R_0402]  54.95 128.43 270 top
PR1107  4.7_1206_5%  [R_1206]  73.24 128.03 180 top
PR1108  3.65K_0603_1%  [R_0603]  49.17 115.85 180 top
PR1110  1_0402_1%  [R_0402]  49.12 116.93 180 top
PR1111  100K_0402_1%  [R_0402]  49.31 128.47 270 top
PR1112  100K_0402_1%  [R_0402]  48.2 126.71 0 top
PR1113  0_0402_5%  [R_0402]  48.2 125.82 0 top
PR1114  1_0603_5%  [R_0603]  57.23 128.93 270 top
PR1115  0_0402_5%  [R0402_0OHM]  48.2 124.04 0 top
PR1116  0_0402_5%  [R0402_0OHM]  48.2 123.15 0 top
PR1117  133K_0402_1%  [R_0402]  48.2 119.59 0 top
PR1119  100K_0402_1%  [R_0402]  48.2 122.26 0 top
PR1120  150K_0402_1%  [R_0402]  47.31 119.63 270 top
PR1121  13.3K_0402_1%  [R_0402]  48.2 118.71 0 top
PR1122  0_0402_5%  [R0402_0OHM]  49.12 121.37 180 top
PR1123  0_0603_5%  [R0603_0OHM]  58.25 120.61 0 top
PR1124  10K_0402_1%  [R_0402]  51.9 112.22 90 top
PR1125  4.7_1206_5%  [R_1206]  72.98 114.06 180 top
PR1126  3.65K_0603_1%  [R_0603]  49.55 112.8 0 top
PR1128  1_0402_1%  [R_0402]  52.79 114.91 270 top
PR1129  301_0402_1%  [R_0402]  55.71 116.37 270 top
PR1130  121K_0402_1%  [R_0402]  59.38 118.71 0 top
PR1131  2.61K_0402_1%  [R_0402]  50.11 113.88 0 top
PR1132  11K_0402_1%  [R_0402]  50.11 114.77 0 top
PR1133  1K_0402_1%  [R_0402]  53.92 115.47 0 top
PR1134  137K_0402_1%  [R_0402]  56.71 116.86 0 top
PR1135  2K_0402_1%  [R_0402]  56.58 115.91 0 top
PR1136  470_0402_1%  [R_0402]  52.15 117.8 90 top
PR1137  100_0402_1%  [R_0402]  53.04 115.9 90 top
PR1138  0_0402_5%  [R0402_0OHM]  53.92 117.75 0 top
PR1139  0_0402_5%  [R0402_0OHM]  56.61 117.75 180 top
PR1140  32.4K_0402_1%  [R_0402]  53.12 127.51 90 top
PR1401  100K_0402_5%  [R_0402]  160.24 87.39 180 bottom
PR1402  0_0603_5%  [R0603_0OHM]  154.96 91.52 90 bottom
PR1403  0_0402_5%  [R0402_0OHM]  160.29 83.63 90 bottom
PR1404  1M_0402_1%  [R_0402]  160.33 85.51 90 bottom
PR1405  0_0402_5%  [R0402_0OHM]  153.41 83.73 90 bottom
PR1406  0_0402_5%  [R_0402]  159.02 83.63 90 bottom
PR1407  0_0402_5%  [R_0402]  158.01 84.55 270 bottom
PR1408  4.7_1206_5%  [R_1206]  151.88 92.12 180 bottom
PR1409  10_0402_5%  [R_0402]  154.29 84.64 270 bottom
PR1410  30.1K_0402_1%  [R_0402]  156.09 84.63 180 bottom
PR1411  24K_0402_1%  [R_0402]  156.99 84.55 270 bottom
PU100  SY8286BRAC_QFN20_3X3  [SY8286BRAC_QFN20_3X3-S]  174.51 48.75 270 bottom
PU102  SY8286CRAC_QFN20_3X3  [SY8286CRAC_QFN20_3X3-S]  196.07 38.71 270 bottom
PU200  RT8207PGQW_WQFN20_3X3  [RT8207PGQW_WQFN20_3X3-S]  88.72 103.95 270 bottom
PU300  S IC RT8237EZQW(2) WDFN 10P  [TPS51212DSCR_SON10_3X3-S]  158.47 30.67 0 top
PU400  RT9059GSP_SO8  [RT904225GSP_SO8]  99.8 14.62 90 bottom
PU600  RT8061AZQW_WDFN10_3X3  [SY8033BDBC_DFN10_3X3-S]  39 103.78 180 bottom
PU703  ISL88739HRZ-T_QFN32_4X4  [ISL95520HRZ-T_QFN32_4X4-S]  215.51 41.09 180 top
PU800  G2992F1U_SO8  [APL5336KAI-TRL_SOP8P8]  131.89 15.64 270 bottom
PU900  RT9059GSP_SO8  [RT904225GSP_SO8]  20.24 97.74 90 bottom
PU1001  ISL62771HRTZ-T_TQFN40_5X5  [ISL62771HRTZ-T_TQFN40_5X5-S]  168.96 58.6 90 top
PU1100  ISL62771HRTZ-T_TQFN40_5X5  [ISL62771HRTZ-T_TQFN40_5X5-S]  51.2 125.04 270 top
PU1400  SY8286RAC_QFN20_3X3  [SY8286RAC_QFN20_3X3-S]  155.23 89.5 270 bottom
Q2  -  [DMN66D0LDW-7_SOT363-6]  150.14 6.26 270 top
Q3  DDTA144VCA-7-F-GP  [2N7002K_SOT23-3]  155.91 10.97 180 top
Q5  -  [2N7002KW_SOT323-3]  154.9 6.53 180 top
Q6  -  [LN2306LT1G_SOT23-3]  91.21 6.09 0 top
Q7  DDTA144VCA-7-F-GP  [2N7002K_SOT23-3]  85.36 5.89 180 top
Q8  -  [LN2306LT1G_SOT23-3]  112.29 7.92 180 top
Q9  -  [LN2306LT1G_SOT23-3]  97.28 5.99 270 top
Q12  NTK3139PT1G_SOT723-3  [2N7002K_SOT23-3]  105.91 10.18 270 top
Q15  DDTA144VCA-7-F-GP  [2N7002K_SOT23-3]  161.76 92.69 90 bottom
Q16  -  [LN2306LT1G_SOT23-3]  163.34 96.26 180 bottom
Q83  -  [2N7002K_SOT23-3]  141.73 13.99 90 bottom
Q84  -  [2N7002K_SOT23-3]  133.88 22.85 180 bottom
Q85  -  [2N7002K_SOT23-3]  105.91 6.11 270 top
Q91  -  [2N7002K_SOT23-3]  187.24 21.61 270 bottom
Q135  AO3416L_SOT23-3  [AO3416_SOT23-3]  133.65 6.62 90 top
Q2407  -  [MMST3904-7-F_SOT323-3]  50.38 12.21 90 bottom
Q2408  -  [MMST3904-7-F_SOT323-3]  115.52 26.69 270 bottom
Q2513  AO3416L_SOT23-3  [AO3416_SOT23-3]  123.97 5.33 0 top
Q2514  AO3416L_SOT23-3  [AO3416_SOT23-3]  119.91 7.41 180 top
Q2515  AO3416L_SOT23-3  [AO3416_SOT23-3]  117.5 12.49 180 top
Q2516  -  [DMN66D0LDW-7_SOT363-6]  132.24 2.37 180 bottom
Q6102  DDTA144VCA-7-F-GP  [2N7002K_SOT23-3]  151.85 10.97 180 top
QA1  -  [LN2306LT1G_SOT23-3]  40.66 8.88 0 top
QC2  -  [MESS138W-G_SOT323-3]  109.75 88.6 0 top
QC79  DMN63D8LDW_SOT363-6  [DMN66D0LDW-7_SOT363-6]  107.83 82.89 0 top
QE4  2N7002KW 1N SOT323-3  [2N7002BKW_SOT323-3]  115.59 8.56 0 top
QI1  -  [2N7002K_SOT23-3]  26.66 96.03 270 top
QI2  -  [DMN66D0LDW-7_SOT363-6]  24.08 91.57 90 top
QI3  -  [MMBT3904_NL_SOT23-3]  26.66 91.97 270 top
QV1  DMN66D0LDW-7 2N SOT363-6  [2N7002KDWH_SOT363-6]  105.22 84.45 180 top
QW1  DII-DMN65D8LW-7~D  [SSM3K7002FU_SC70-3]  56.41 106.12 180 top
R4  0_0805_5%  [R_0805]  223.64 48.85 0 top
R5  0_0402_5%  [R_0402]  219.81 48.02 180 bottom
R6  0_0402_5%  [R0402_0OHM]  221.71 48.02 180 bottom
R7  0_0402_5%  [R0402_0OHM]  221.71 35.83 180 bottom
R11  0_0603_5%  [R_0603]  228.11 35.01 270 top
R12  0_0603_5%  [R_0603]  229.38 35.01 270 top
R13  0_0402_5%  [R0402_0OHM]  221.71 47.01 180 bottom
R14  0_0603_1%  [R0603_0OHM]  227.92 32.28 180 top
R16  0_0603_1%  [R0603_0OHM]  225.64 36.34 0 top
R17  0_0402_5%  [R_0402-NPM]  220.8 33.8 0 bottom
R18  0_0402_5%  [R_0402-NPM]  220.8 34.82 0 bottom
R23  10K_0402_5%  [R_0402]  153.12 4.64 90 top
R27  1K_0402_5%  [R_0402]  85.36 8.2 90 top
R28  100K_0402_5%  [R_0402]  91.66 9.92 180 top
R31  4.7K_0402_5%  [R_0402]  103.19 5.61 0 top
R32  4.7K_0402_5%  [R_0402]  102.33 5.61 180 top
R35  0_0402_5%  [R_0402]  111.73 10.69 180 top
R36  0_0402_5%  [R_0402]  88.67 8.2 90 top
R37  0_0402_5%  [R0402_0OHM]  87.65 9.11 270 top
R38  100_0603_1%  [R_0603]  104.03 7.64 90 top
R39  20K_0402_1%  [R_0402]  111.73 9.67 180 top
R41  100K_0402_5%  [R_0402]  103.21 10.1 90 top
R51  0_0805_5%  [R0805_0OHM]  222.02 50.91 270 bottom
R53  100K_0402_5%  [R_0402]  162.88 100.35 0 bottom
R54  1K_0402_5%  [R_0402]  121.05 4.7 90 bottom
R56  1K_0402_5%  [R_0402]  121.13 3.83 180 bottom
R150  0_0402_5%  [R_0402]  95.52 4.64 90 top
R437  1K_0402_5%  [R_0402]  160.29 18.1 90 bottom
R438  33K_0402_5%  [R_0402]  105.47 96.72 180 bottom
R439  10K_0402_5%  [R_0402]  107.46 93.19 270 bottom
R1563  100K_0402_5%  [R_0402]  179.6 20.54 270 bottom
R1671  470_0603_5%  [R_0603]  139.53 16.02 0 bottom
R1674  4.7K_0402_5%  [R_0402]  136.42 22.07 270 bottom
R2313  0_0402_5%  [R_0402]  161.31 18.1 90 bottom
R2318  0_0402_5%  [R_0402]  160.75 20.08 180 bottom
R2448  10K_0402_5%  [R_0402]  80.49 12.46 180 top
R2450  0_0402_5%  [R_0402]  79.57 13.48 0 top
R2634  100K_0402_5%  [R_0402]  131.54 5.35 180 bottom
R2635  100K_0402_5%  [R_0402]  120.21 6.62 0 bottom
R2636  100K_0402_5%  [R_0402]  120.21 2.81 0 bottom
RA1  0_0805_5%  [R0805_0OHM]  37.61 34.14 270 top
RA2  0_0805_5%  [R0805_0OHM]  35.4 36.47 180 top
RA4  0_0603_1%  [R0603_0OHM]  17.04 26.62 270 top
RA5  0_0402_5%  [R0402_0OHM]  36.55 23.64 180 top
RA6  0_0402_5%  [R_0402]  38.12 10.99 90 top
RA7  0_0402_5%  [R_0402]  37.17 10.99 90 top
RA8  100K_0402_5%  [R_0402]  32.41 31.46 270 top
RA10  100K_0402_5%  [R_0402]  22.38 32.38 90 top
RA11  0_0402_5%  [R0402_0OHM]  28.98 13.68 270 top
RA12  0_0402_5%  [R_0402]  29.99 13.68 270 top
RA13  100K_0402_5%  [R_0402]  24.47 21.62 270 top
RA14  0_0402_5%  [R_0402]  23.29 33.55 270 top
RA15  0_0402_5%  [R0402_0OHM]  24.18 33.56 270 top
RA16  0_0402_5%  [R_0402]  25.06 33.56 270 top
RA17  0_0402_5%  [R0402_0OHM]  20.34 32.07 90 top
RA18  0_0402_5%  [R0402_0OHM]  26.94 13.18 270 top
RA19  0_0402_5%  [R0402_0OHM]  4.72 25.6 90 top
RA20  0_0402_5%  [R0402_0OHM]  15.77 25.47 90 top
RA21  0_0402_5%  [R0402_0OHM]  31.26 18.86 90 top
RA22  0_0805_5%  [R0805_0OHM]  34.98 14.75 0 top
RA25  2.2K_0402_5%  [R_0402]  22.63 14.17 90 bottom
RA26  2.2K_0402_5%  [R_0402]  22.63 16.83 90 bottom
RA27  10_0402_1%  [R_0402]  23.9 14.19 270 top
RA28  1K_0402_5%  [R_0402]  24.91 14.19 270 top
RA29  4.7K_0402_5%  [R_0402]  25.93 14.19 270 top
RA30  10K_0402_5%  [R_0402]  21.61 14.19 270 top
RA31  10_0402_1%  [R_0402]  23.9 16.83 90 top
RA32  1K_0402_5%  [R_0402]  24.91 16.83 90 top
RA33  4.7K_0402_5%  [R_0402]  25.93 16.83 90 top
RA34  10K_0402_5%  [R_0402]  21.61 16.83 90 top
RA40  0_0402_5%  [R0402_0OHM]  13.85 25.23 0 top
RA41  200K_0402_1%  [R_0402]  22.58 31.01 180 top
RA42  0_0603_1%  [R0603_0OHM]  20.34 31.2 270 top
RA43  33_0402_5%  [R_0402]  26.87 32.64 90 top
RA44  0_0402_5%  [R_0402]  29.03 32.28 0 top
RA45  10K_0402_5%  [R_0402]  18.87 26.94 0 top
RA49  1K_0402_1%  [R_0402]  19.78 27.96 180 top
RA55  33_0402_5%  [R_0402]  30.88 34.77 270 top
RA56  0_0402_5%  [R_0402]  29.97 35.96 180 top
RC1  100K_0402_5%  [R_0402]  109.75 32.07 90 bottom
RC2  1K_0402_5%  [R_0402]  172.18 61.36 180 bottom
RC4  4.7K_0402_5%  [R_0402]  123.21 83.38 90 top
RC5  1K_0402_1%  [R_0402]  93.62 55.72 270 top
RC6  1K_0402_5%  [R_0402]  95.46 56.61 270 top
RC7  4.7K_0402_5%  [R_0402]  128.87 89.43 180 bottom
RC8  1K_0402_1%  [R_0402]  94.51 56.61 270 top
RC9  1K_0402_5%  [R_0402]  133.8 78.76 0 top
RC10  1K_0402_5%  [R_0402]  133.8 77.87 0 top
RC11  0_0402_5%  [R_0402]  121.76 24.58 180 top
RC12  0_0402_5%  [R_0402]  140.02 45.99 0 top
RC13  1K_0402_5%  [R_0402]  103.86 20.59 180 top
RC16  1K_0402_5%  [R_0402]  110.26 84.04 270 top
RC17  1K_0402_5%  [R_0402]  106.7 84.8 270 top
RC18  0_0402_5%  [R0402_0OHM]  121.75 23.5 180 top
RC21  4.7K_0402_5%  [R_0402]  133.93 55.9 0 top
RC22  0_0402_5%  [R0402_0OHM]  140.02 47.01 0 top
RC23  0_0402_5%  [R_0402]  113.49 48.04 270 top
RC25  33_0402_5%  [R_0402]  110 28.9 90 bottom
RC26  8.2K_0402_5%  [R_0402]  108.73 23.94 90 bottom
RC27  0_0402_5%  [R_0402]  111.78 32.07 90 bottom
RC28  0_0402_5%  [R_0402]  109.06 29.8 180 bottom
RC29  0_0402_5%  [R_0402]  107.46 63.95 90 top
RC30  0_0402_5%  [R_0402]  109.06 28.91 180 bottom
RC31  1K_0402_5%  [R_0402]  30.7 7.38 180 bottom
RC32  0_0402_5%  [R0402_0OHM]  108.41 63.95 90 top
RC33  1K_0402_5%  [R_0402]  134.84 51.83 180 bottom
RC40  15K_0402_5%  [R_0402]  132.62 50.82 180 bottom
RC41  15K_0402_5%  [R_0402]  132.62 51.83 180 bottom
RC42  15K_0402_5%  [R_0402]  132.56 47.33 180 bottom
RC43  10K_0402_5%  [R_0402]  112.29 23.44 90 top
RC44  10K_0402_5%  [R_0402]  114.32 23.44 90 top
RC45  10K_0402_5%  [R_0402]  113.3 23.44 90 top
RC46  10K_0402_5%  [R_0402]  98.78 24.85 180 top
RC48  10K_0402_5%  [R_0402]  117.51 30.5 180 bottom
RC49  10K_0402_5%  [R_0402]  111.27 23.44 90 top
RC50  10K_0402_5%  [R_0402]  108.22 32.07 90 bottom
RC51  0_0402_5%  [R_0402]  141.38 51.77 180 top
RC52  0_0402_5%  [R0402_0OHM]  140.47 50.75 0 top
RC53  0_0402_5%  [R0402_0OHM]  137.89 55.39 180 top
RC54  0_0402_5%  [R_0402]  122.19 84.3 270 top
RC55  10K_0402_5%  [R_0402]  114.96 34.36 90 bottom
RC56  0_0402_5%  [R_0402]  106.12 26.18 0 bottom
RC57  0_0402_5%  [R_0402]  127.22 92.47 180 bottom
RC58  0_0402_5%  [R_0402]  115.84 83.89 90 top
RC59  0_0402_5%  [R_0402]  115.54 85.74 180 top
RC60  0_0402_5%  [R_0402]  111.53 88.36 270 top
RC61  10K_0402_5%  [R_0402]  114.07 34.36 90 bottom
RC70  2.2K_0402_5%  [R_0402]  107.97 88.36 270 top
RC75  39.2_0402_1%  [R_0402]  95.22 52.34 180 top
RC80  300_0402_5%  [R_0402]  128.87 90.32 180 bottom
RC81  300_0402_5%  [R_0402]  124.23 83.38 90 top
RC90  1K_0402_1%  [R_0402]  119.41 45.43 225 top
RC93  1K_0402_5%  [R_0402]  128.72 24.1 270 top
RC96  1K_0402_1%  [R_0402]  119.48 46.5 180 top
RC106  33_0402_5%  [R_0402]  119.65 34.36 90 bottom
RC117  1K_0402_5%  [R_0402]  109.3 65.98 90 top
RC118  1K_0402_5%  [R_0402]  109.3 64.86 270 top
RC119  0_0402_5%  [R0402_0OHM]  112.16 38.55 90 top
RC154  1K_0402_5%  [R_0402]  113.62 62.32 270 top
RC155  1K_0402_5%  [R_0402]  113.35 63.84 0 top
RC159  1K_0402_5%  [R_0402]  108.48 71.6 270 bottom
RC346  22K_0402_5%  [R_0402]  133.88 49.48 0 top
RC350  4.7K_0402_5%  [R_0402]  133.93 56.91 0 top
RC400  2K_0402_1%  [R_0402]  116.35 64.86 270 top
RC401  150_0402_1%  [R_0402]  115.83 62.63 0 top
RC449  33_0402_5%  [R_0402]  112.73 34.36 90 bottom
RC450  33_0402_5%  [R_0402]  114.07 30.93 90 bottom
RC458  0_0402_5%  [R0402_0OHM]  94.56 54.69 0 top
RC541  196_0402_1%  [R_0402]  133.93 52.85 0 top
RC542  196_0402_1%  [R_0402]  134.84 54.88 180 top
RC602  33_0402_5%  [R_0402]  111.84 34.36 90 bottom
RC617  10_0402_5%  [R_0402]  121.98 20.41 90 bottom
RC639  10K_0402_5%  [R_0402]  118.89 26.36 90 bottom
RC640  10K_0402_5%  [R_0402]  117.69 26.36 90 bottom
RC641  11.8K_0402_1%  [R_0402]  122.33 46.88 180 top
RC642  10K_0402_5%  [R_0402]  121.23 18.81 0 bottom
RC643  10K_0402_5%  [R_0402]  131.71 53.36 0 bottom
RC644  1K_0402_1%  [R_0402]  133.93 53.87 0 top
RC645  1K_0402_1%  [R_0402]  133.93 57.87 0 top
RC646  10K_0402_5%  [R_0402]  115.84 35.27 270 bottom
RC654  100K_0402_5%  [R_0402]  134.84 66.44 180 top
RC661  0_0402_5%  [R_0402]  120.67 35.27 270 bottom
RC662  0_0402_5%  [R_0402]  136.47 43.71 0 top
RC663  0_0402_5%  [R_0402]  133.93 46.31 0 bottom
RC664  0_0402_5%  [R_0402]  130.27 52.47 180 bottom
RC665  0_0402_5%  [R0402_0OHM]  111.27 38.83 270 top
RC666  0_0402_5%  [R_0402]  111.27 40.61 270 top
RC669  0_0402_5%  [R_0402]  113.05 66.01 270 top
RC670  0_0402_5%  [R_0402]  112.03 66.01 270 top
RC673  0_0402_5%  [R_0402]  171.28 62.24 90 bottom
RC678  2.2K_0402_5%  [R_0402]  134.84 50.82 180 bottom
RC683  2.2K_0402_5%  [R_0402]  134.84 47.33 180 bottom
RC690  4.7K_0402_5%  [R_0402]  114.83 84.8 270 top
RC691  4.7K_0402_5%  [R_0402]  115.79 82.82 180 top
RC692  10K_0402_5%  [R_0402]  137.38 50.82 180 top
RC693  10K_0402_5%  [R_0402]  133.93 50.82 0 top
RC694  10K_0402_5%  [R_0402]  132.62 54.88 180 bottom
RC695  10K_0402_5%  [R_0402]  134.59 34.87 180 bottom
RC696  10K_0402_5%  [R_0402]  134.59 35.78 180 bottom
RC697  10K_0402_5%  [R_0402]  108.8 47.85 270 top
RC703  10K_0402_5%  [R_0402]  134.59 33.93 180 bottom
RC706  10K_0402_5%  [R_0402]  103.86 19.58 180 top
RC707  10K_0402_5%  [R_0402]  137.38 45.99 180 top
RC708  10K_0402_5%  [R_0402]  134.84 45.99 180 top
RC709  10K_0402_5%  [R_0402]  110.38 37.41 90 bottom
RC710  10K_0402_5%  [R_0402]  110.26 35.27 270 bottom
RC711  10K_0402_5%  [R_0402]  132.56 45.23 180 bottom
RC712  10K_0402_5%  [R_0402]  133.93 45.23 0 bottom
RC902  10K_0402_5%  [R_0402]  115.84 32.07 90 bottom
RC903  2K_0402_5%  [R_0402]  117.5 32.07 90 bottom
RC904  10K_0402_5%  [R_0402]  112.73 32.07 90 bottom
RC905  100K_0402_5%  [R_0402]  132.62 55.9 180 bottom
RC906  100K_0402_5%  [R_0402]  134.84 49.55 180 bottom
RC907  33_0402_5%  [R_0402]  134.84 51.83 180 top
RC914  20M_0402_5%  [R_0402]  134.64 38.58 270 bottom
RC925  10K_0402_5%  [R_0402]  114.96 31.84 270 bottom
RC926  2K_0402_5%  [R_0402]  112.29 29.69 270 bottom
RC927  2K_0402_5%  [R_0402]  114.19 29.69 270 bottom
RC928  10K_0402_5%  [R_0402]  133.93 48.02 0 top
RC929  2K_0402_5%  [R_0402]  136.47 48.02 0 top
RC932  10K_0402_5%  [R_0402]  140.94 48.02 180 top
RC933  10K_0402_5%  [R_0402]  132.56 44.21 180 bottom
RC938  10K_0402_5%  [R_0402]  109.24 34.36 90 bottom
RC939  1M_0402_5%  [R_0402]  130.58 62.3 90 bottom
RC942  10K_0402_5%  [R_0402]  135.1 53.36 180 bottom
RC943  100K_0402_5%  [R_0402]  140.94 48.91 180 top
RC944  10K_0402_5%  [R_0402]  134.84 55.9 180 bottom
RC949  10K_0402_5%  [R_0402]  133.93 44.98 0 top
RC950  2K_0402_5%  [R_0402]  136.47 44.98 0 top
RC951  10K_0402_5%  [R_0402]  130.27 50.82 180 bottom
RC952  2.2K_0402_5%  [R_0402]  132.62 49.55 180 bottom
RC953  2.2K_0402_5%  [R_0402]  136.47 47.01 0 top
